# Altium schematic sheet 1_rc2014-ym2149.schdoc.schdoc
size 289 x 200 mm; Name: default297x210; Symbol: default297x210; Device: default297x210; Size: &quot;A4&quot;; Id: /; File: rc2014-ym2149; Sheet: /
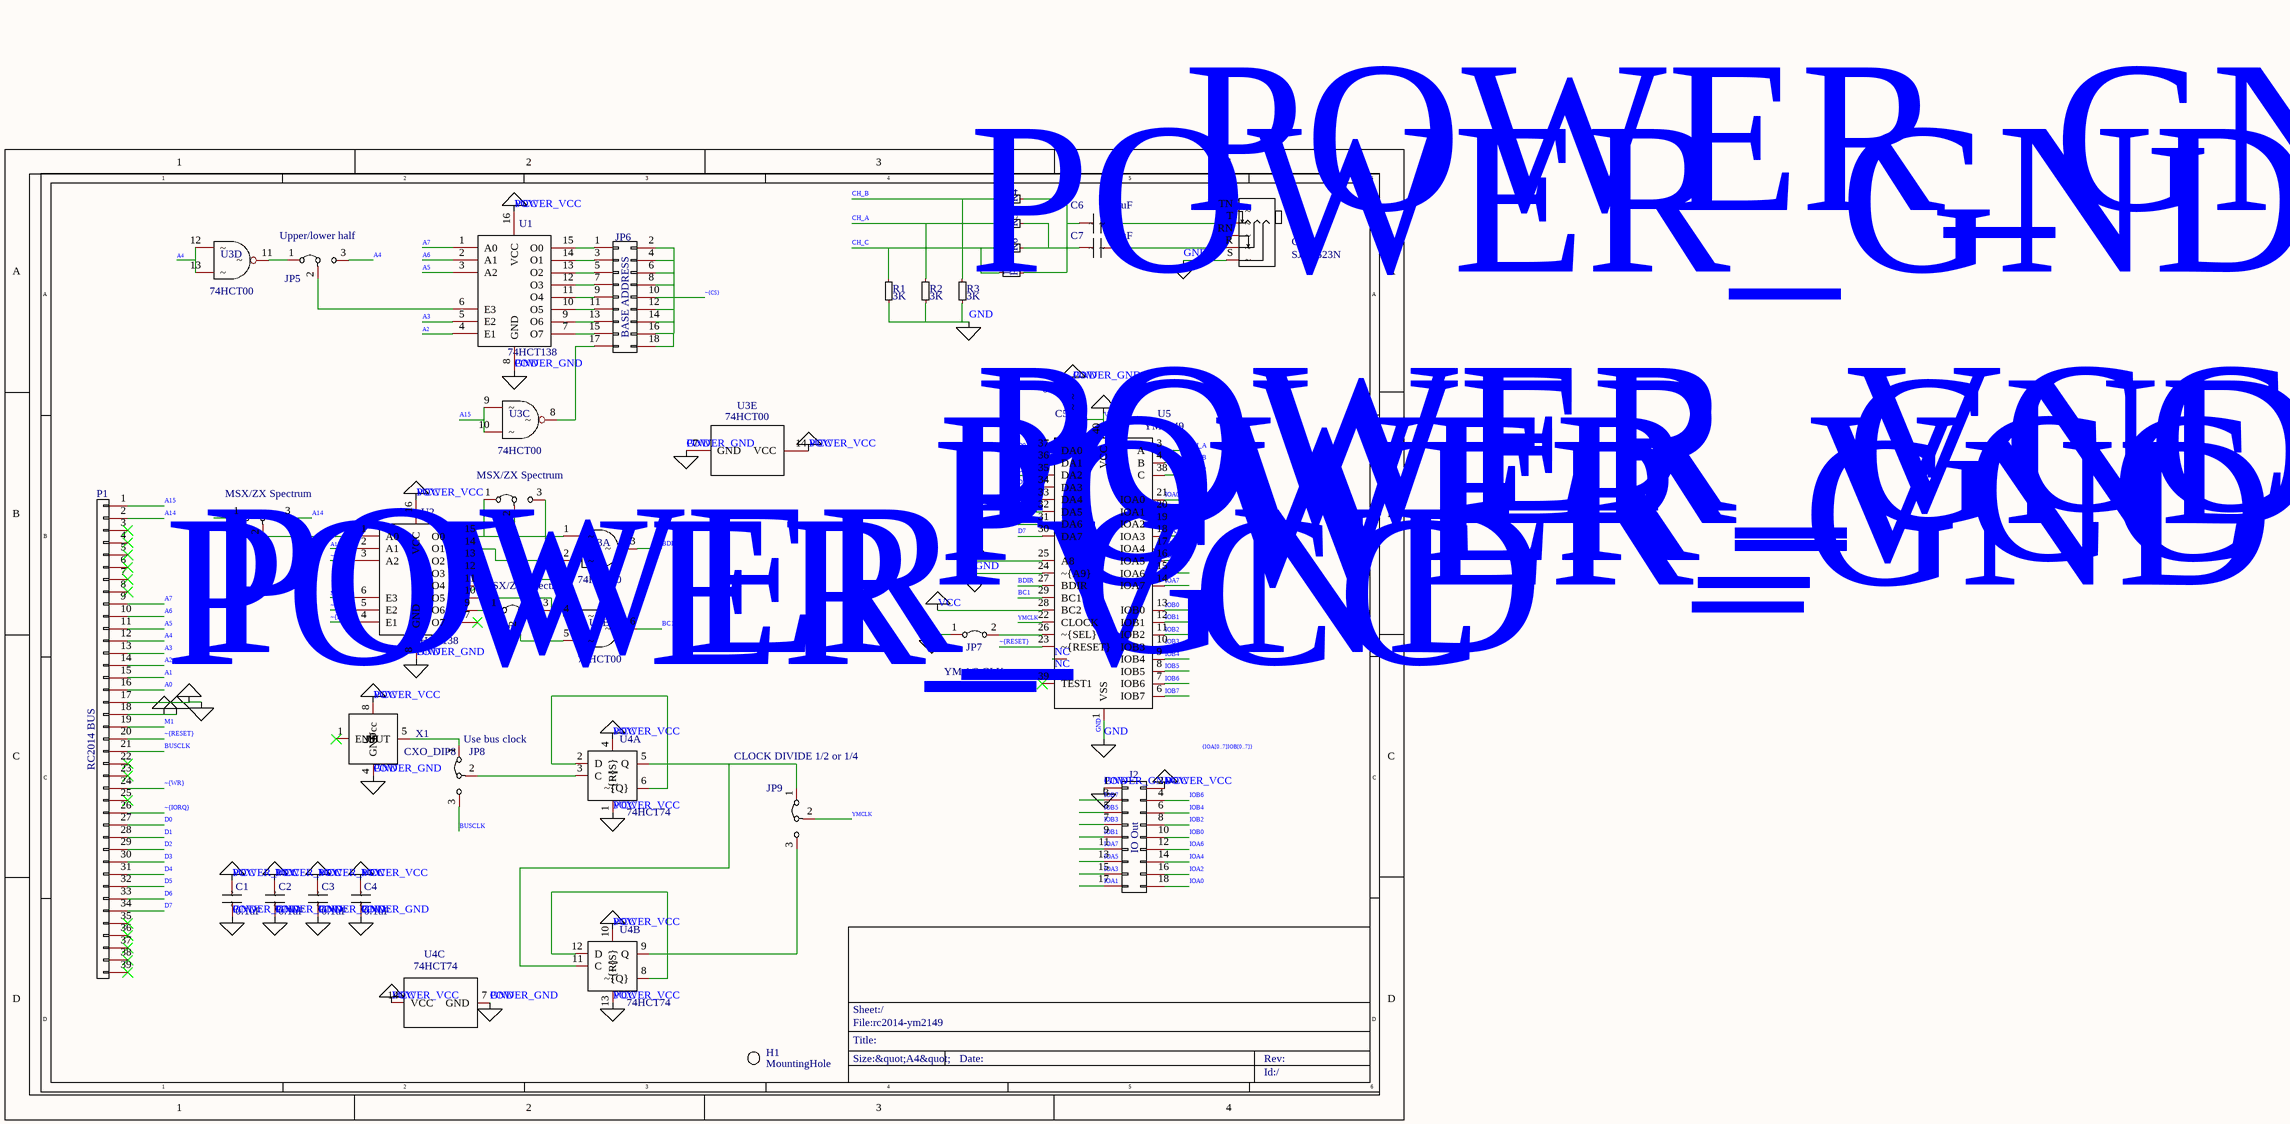
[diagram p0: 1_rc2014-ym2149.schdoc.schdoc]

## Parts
(Parts that share a designator on the sheet are numbered #1, #2 ... from top to bottom, then left to right.)
C1  value 0.1uF  [Capacitor_THT:C_Disc_D3.8mm_W2.6mm_P2.50mm]  (hidden comment: Device_C)
C2  value 0.1uF  [Capacitor_THT:C_Disc_D3.8mm_W2.6mm_P2.50mm]  (hidden comment: Device_C)
C3  value 0.1uF  [Capacitor_THT:C_Disc_D3.8mm_W2.6mm_P2.50mm]  (hidden comment: Device_C)
C4  value 0.1uF  [Capacitor_THT:C_Disc_D3.8mm_W2.6mm_P2.50mm]  (hidden comment: Device_C)
C5  value 0.1uF  [Capacitor_THT:C_Disc_D3.8mm_W2.6mm_P2.50mm]  (hidden comment: Device_C)
C6  value 4.7uF  [Capacitor_THT:CP_Radial_D6.3mm_P2.50mm]  (hidden comment: Device_C)
C7  value 4.7uF  [Capacitor_THT:CP_Radial_D6.3mm_P2.50mm]  (hidden comment: Device_C)
CON1  value SJ1-3523N  [rc2014:Headphone_Jack_3.5mm_5_pin]  (hidden comment: Connector_Audio_AudioJack3_SwitchTR)
H1  value MountingHole  [MountingHole:MountingHole_3.2mm_M3]  (hidden comment: Mechanical_MountingHole)
J2  value IO Out  [Connector_PinHeader_2.54mm:PinHeader_2x09_P2.54mm_Vertical]  (hidden comment: Connector_Generic_Conn_02x09_Odd_Even)
JP1  value MSX/ZX Spectrum  [Connector_PinHeader_2.54mm:PinHeader_1x03_P2.54mm_Vertical]  (hidden comment: Jumper_Jumper_3_Bridged12)
JP2  value MSX/ZX Spectrum  [Connector_PinHeader_2.54mm:PinHeader_1x03_P2.54mm_Vertical]  (hidden comment: Jumper_Jumper_3_Bridged12)
JP3  value MSX/ZX Spectrum  [Connector_PinHeader_2.54mm:PinHeader_1x03_P2.54mm_Vertical]  (hidden comment: Jumper_Jumper_3_Bridged12)
JP5  value Upper/lower half  [Connector_PinHeader_2.54mm:PinHeader_1x03_P2.54mm_Vertical]  (hidden comment: Jumper_Jumper_3_Bridged12)
JP6  value BASE ADDRESS  [Connector_PinHeader_2.54mm:PinHeader_2x09_P2.54mm_Vertical]  (hidden comment: Connector_Generic_Conn_02x09_Odd_Even)
JP7  value YM 1/2 CLK  [Connector_PinHeader_2.54mm:PinHeader_1x02_P2.54mm_Vertical]  (hidden comment: Jumper_Jumper_2_Bridged)
JP8  value Use bus clock  [Connector_PinHeader_2.54mm:PinHeader_1x03_P2.54mm_Vertical]  (hidden comment: Jumper_Jumper_3_Bridged12)
JP9  value CLOCK DIVIDE 1/2 or 1/4  [Connector_PinHeader_2.54mm:PinHeader_1x03_P2.54mm_Vertical]  (hidden comment: Jumper_Jumper_3_Bridged12)
P1  value RC2014 BUS  [rc2014:PinHeader_1x39_P2.54mm_Vertical]  (hidden comment: Connector_Generic_Conn_01x39)
R1  value 3K  [Resistor_THT:R_Axial_DIN0207_L6.3mm_D2.5mm_P10.16mm_Horizontal]  (hidden comment: Device_R_Small)
R2  value 3K  [Resistor_THT:R_Axial_DIN0207_L6.3mm_D2.5mm_P10.16mm_Horizontal]  (hidden comment: Device_R_Small)
R3  value 3K  [Resistor_THT:R_Axial_DIN0207_L6.3mm_D2.5mm_P10.16mm_Horizontal]  (hidden comment: Device_R_Small)
R4  value 1K  [Resistor_THT:R_Axial_DIN0207_L6.3mm_D2.5mm_P10.16mm_Horizontal]  (hidden comment: Device_R_Small)
R5  value 1K  [Resistor_THT:R_Axial_DIN0207_L6.3mm_D2.5mm_P10.16mm_Horizontal]  (hidden comment: Device_R_Small)
R6  value 1K6  [Resistor_THT:R_Axial_DIN0207_L6.3mm_D2.5mm_P10.16mm_Horizontal]  (hidden comment: Device_R_Small)
R7  value 1K6  [Resistor_THT:R_Axial_DIN0207_L6.3mm_D2.5mm_P10.16mm_Horizontal]  (hidden comment: Device_R_Small)
U1  value 74HCT138  [Package_DIP:DIP-16_W7.62mm_Socket_LongPads]  (hidden comment: 74xx_74LS138)
U2  value 74HCT138  [Package_DIP:DIP-16_W7.62mm_Socket_LongPads]  (hidden comment: 74xx_74LS138)
U3  value 74HCT00  (hidden comment: 74xx_74HCT00)  (parts A,B,C,D,E of 5)
U4#1  value 74HCT74  (hidden comment: 74xx_74LS74)  (parts A,B of 3)
U4#2  value 74HCT74  [Package_DIP:DIP-14_W7.62mm_Socket_LongPads]  (hidden comment: 74xx_74HC74)  (part C of 3)
U5  value YM2149  [Package_DIP:DIP-40_W15.24mm_Socket_LongPads]  (hidden comment: Audio_YM2149)
X1  value CXO_DIP8  [Package_DIP:DIP-8_W7.62mm_Socket_LongPads]  (hidden comment: Oscillator_CXO_DIP8)

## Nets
GND: C1.1 C1.2 C2.1 C2.2 C3.1 C3.2 C4.1 C4.2 C5.1 C5.2 CON1.S J2.1(Pin_1) J2.2(Pin_2) JP7.1(A) P1.17(Pin_17) P1.18(Pin_18) R1.2 R2.2 R3.2 U1.8(GND) U1.16(VCC) U2.8(GND) U2.16(VCC) U3.7(GND) U3.14(VCC) U4#1.1(~{R}) U4#1.4(~{S}) U4#1.10(~{S}) U4#1.13(~{R}) U4#2.7(GND) U4#2.14(VCC) U5.1(VSS) U5.24(~{A9}) U5.25(A8) U5.28(BC2) U5.40(VCC) X1.4(GND) X1.8(Vcc)  [also labelled POWER_GND, POWER_PWR_FLAG, POWER_VCC, VCC]
A0: JP1.1(A) P1.16(Pin_16)
A1: P1.15(Pin_15) U2.2(A1)
A2: P1.14(Pin_14) U1.4(E1)
A3: P1.13(Pin_13) U1.5(E2)
A4: JP5.3(B) P1.12(Pin_12) U3.12 U3.13
A5: P1.11(Pin_11) U1.3(A2)
A6: P1.10(Pin_10) U1.2(A1)
A7: P1.9(Pin_9) U1.1(A0)
A14: JP1.3(B) P1.2(Pin_2)
A15: P1.1(Pin_1) U3.9 U3.10
BC1: U3.6 U5.29(BC1)
BDIR: U3.3 U5.27(BDIR)
BUSCLK: JP8.3(B) P1.21(Pin_21)
CH_A: R2.1 R5.2 U5.3(A)
CH_B: R3.1 R4.2 U5.4(B)
CH_C: R1.1 R6.2 R7.2 U5.38(C)
D0: P1.27(Pin_27) U5.37(DA0)
D1: P1.28(Pin_28) U5.36(DA1)
D2: P1.29(Pin_29) U5.35(DA2)
D3: P1.30(Pin_30) U5.34(DA3)
D4: P1.31(Pin_31) U5.33(DA4)
D5: P1.32(Pin_32) U5.32(DA5)
D6: P1.33(Pin_33) U5.31(DA6)
D7: P1.34(Pin_34) U5.30(DA7)
IOA0: J2.18(Pin_18) U5.21(IOA0)
IOA1: J2.17(Pin_17) U5.20(IOA1)
IOA2: J2.16(Pin_16) U5.19(IOA2)
IOA3: J2.15(Pin_15) U5.18(IOA3)
IOA4: J2.14(Pin_14) U5.17(IOA4)
IOA5: J2.13(Pin_13) U5.16(IOA5)
IOA6: J2.12(Pin_12) U5.15(IOA6)
IOA7: J2.11(Pin_11) U5.14(IOA7)
IOB0: J2.10(Pin_10) U5.13(IOB0)
IOB1: J2.9(Pin_9) U5.12(IOB1)
IOB2: J2.8(Pin_8) U5.11(IOB2)
IOB3: J2.7(Pin_7) U5.10(IOB3)
IOB4: J2.6(Pin_6) U5.9(IOB4)
IOB5: J2.5(Pin_5) U5.8(IOB5)
IOB6: J2.4(Pin_4) U5.7(IOB6)
IOB7: J2.3(Pin_3) U5.6(IOB7)
M1: P1.19(Pin_19) U2.6(E3)
NC: U5.2(NC) U5.5(NC)
YMCLK: JP9.2(C) U5.22(CLOCK)
~{CS}: JP6.2(Pin_2) JP6.4(Pin_4) JP6.6(Pin_6) JP6.8(Pin_8) JP6.10(Pin_10) JP6.12(Pin_12) JP6.14(Pin_14) JP6.16(Pin_16) JP6.18(Pin_18) U2.5(E2)
~{IORQ}: P1.26(Pin_26) U2.4(E1)
~{RESET}: P1.20(Pin_20) U5.23(~{RESET})
~{WR}: P1.24(Pin_24) U2.3(A2)
NetC6_1: C6.1 R4.1 R7.1
NetC6_2: C6.2 CON1.T CON1.TN
NetC7_1: C7.1 R5.1 R6.1
NetC7_2: C7.2 CON1.R CON1.RN
NetJP1_2: JP1.2(C) U2.1(A0)
NetJP2_1: JP2.1(A) U2.15(O0) U3.1
NetJP2_2: JP2.2(C) U3.4
NetJP2_3: JP2.3(B) U2.14(O1) U3.2
NetJP3_1: JP3.1(A) U2.9(O6)
NetJP3_2: JP3.2(C) U3.5
NetJP3_3: JP3.3(B) U2.10(O5)
NetJP5_1: JP5.1(A) U3.11
NetJP5_2: JP5.2(C) U1.6(E3)
NetJP6_1: JP6.1(Pin_1) U1.15(O0)
NetJP6_3: JP6.3(Pin_3) U1.14(O1)
NetJP6_5: JP6.5(Pin_5) U1.13(O2)
NetJP6_7: JP6.7(Pin_7) U1.12(O3)
NetJP6_9: JP6.9(Pin_9) U1.11(O4)
NetJP6_11: JP6.11(Pin_11) U1.10(O5)
NetJP6_13: JP6.13(Pin_13) U1.9(O6)
NetJP6_15: JP6.15(Pin_15) U1.7(O7)
NetJP6_17: JP6.17(Pin_17) U3.8
NetJP7_2: JP7.2(B) U5.26(~{SEL})
NetJP8_1: JP8.1(A) X1.5(OUT)
NetJP8_2: JP8.2(C) U4#1.3(C)
NetJP9_1: JP9.1(A) U4#1.5(Q) U4#1.11(C)
NetJP9_3: JP9.3(B) U4#1.9(Q)
NetU4#1_2: U4#1.2(D) U4#1.6(~{Q})
NetU4#1_8: U4#1.8(~{Q}) U4#1.12(D)

Not connected (* = marked no-connect by the designer): P1 3(Pin_3)* 4(Pin_4)* 5(Pin_5)* 6(Pin_6)* 7(Pin_7)* 8(Pin_8)* 22(Pin_22)* 23(Pin_23)* 25(Pin_25)* 35(Pin_35)* 36(Pin_36)* 37(Pin_37)* 38(Pin_38)* 39(Pin_39)*; U2 7(O7)* 11(O4)* 12(O3)* 13(O2)*; U5 39(TEST1)*; X1 1(EN)*

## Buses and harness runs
bus {IOA[0..7]IOB[0..7]}

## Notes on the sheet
- Labels drawn without touching a wire or pin: {IOA[0..7]IOB[0..7]}

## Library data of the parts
C1-C5 = Device_C: Add into BOM: yes; Origin Footprint: C_Disc_D3.8mm_W2.6mm_P2.50mm
C6 C7 = Device_C: Add into BOM: yes; Origin Footprint: CP_Radial_D6.3mm_P2.50mm
CON1 = Connector_Audio_AudioJack3_SwitchTR: Add into BOM: yes; Origin Footprint: Headphone_Jack_3.5mm_5_pin
H1 = Mechanical_MountingHole: Add into BOM: yes; Origin Footprint: MountingHole_3.2mm_M3
J2 = Connector_Generic_Conn_02x09_Odd_Even: IO Out; Add into BOM: yes; Origin Footprint: PinHeader_2x09_P2.54mm_Vertical
JP1-JP3 = Jumper_Jumper_3_Bridged12: MSX/ZX Spectrum; Add into BOM: yes; Origin Footprint: PinHeader_1x03_P2.54mm_Vertical
JP5 = Jumper_Jumper_3_Bridged12: Upper/lower half; Add into BOM: yes; Origin Footprint: PinHeader_1x03_P2.54mm_Vertical
JP6 = Connector_Generic_Conn_02x09_Odd_Even: Base Address; Add into BOM: yes; Origin Footprint: PinHeader_2x09_P2.54mm_Vertical
JP7 = Jumper_Jumper_2_Bridged: YM 1/2 CLK; Add into BOM: yes; Origin Footprint: PinHeader_1x02_P2.54mm_Vertical
JP8 = Jumper_Jumper_3_Bridged12: Use bus clock or on board oscillator; Add into BOM: yes; Origin Footprint: PinHeader_1x03_P2.54mm_Vertical
JP9 = Jumper_Jumper_3_Bridged12: Clock Divide 1/2 or 1/4; Add into BOM: yes; Origin Footprint: PinHeader_1x03_P2.54mm_Vertical
P1 = Connector_Generic_Conn_01x39: RC2014 BUS; Add into BOM: yes; Origin Footprint: PinHeader_1x39_P2.54mm_Vertical
R1-R7 = Device_R_Small: Add into BOM: yes; Origin Footprint: R_Axial_DIN0207_L6.3mm_D2.5mm_P10.16mm_Horizontal
U1 U2 = 74xx_74LS138: Add into BOM: yes; Origin Footprint: DIP-16_W7.62mm_Socket_LongPads
U3 = 74xx_74HCT00: Add into BOM: yes; Origin Footprint: DIP-14_W7.62mm_Socket_LongPads
U4#1 = 74xx_74LS74: Add into BOM: yes; Origin Footprint: DIP-14_W7.62mm_Socket_LongPads
U4#2 = 74xx_74HC74: Add into BOM: yes; Origin Footprint: DIP-14_W7.62mm_Socket_LongPads
U5 = Audio_YM2149: Add into BOM: yes; Origin Footprint: DIP-40_W15.24mm
X1 = Oscillator_CXO_DIP8: Optional oscillator; Add into BOM: yes; Origin Footprint: Oscillator_DIP-8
